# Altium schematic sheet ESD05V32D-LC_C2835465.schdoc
size 127 x 101 mm
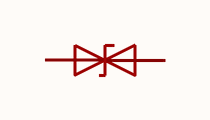
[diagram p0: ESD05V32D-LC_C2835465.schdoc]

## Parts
D?  esd05v32d-lc_c2835465  [SOD-323_L1.8-W1.3-LS2.5-BI]  (value not drawn)

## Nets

Not connected (* = marked no-connect by the designer): D? 1(K) 2(A)

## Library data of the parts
D? = esd05v32d-lc_c2835465: 极性:双向;反向截止电压(Vrwm):5V;钳位电压:19V;击穿电压:8V;; Manufacturer: TECH PUBLIC(台舟); AddInBom: yes; ModelId: f9eb3c564310447fa7e5a2d35bef3787; ModelTransform: 98.425,51.181,0,0,0,0,0,0,0; Polarity: 双向; Reverse Stand-Off Voltage (Vrwm): 5V; Clamping Voltage: 19V; Voltage - Breakdown: 8V; Reverse Leakage Current (Ir): 200nA; Number of Channels: 单路; Type: ESD; Junction Capacitance: 3pF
